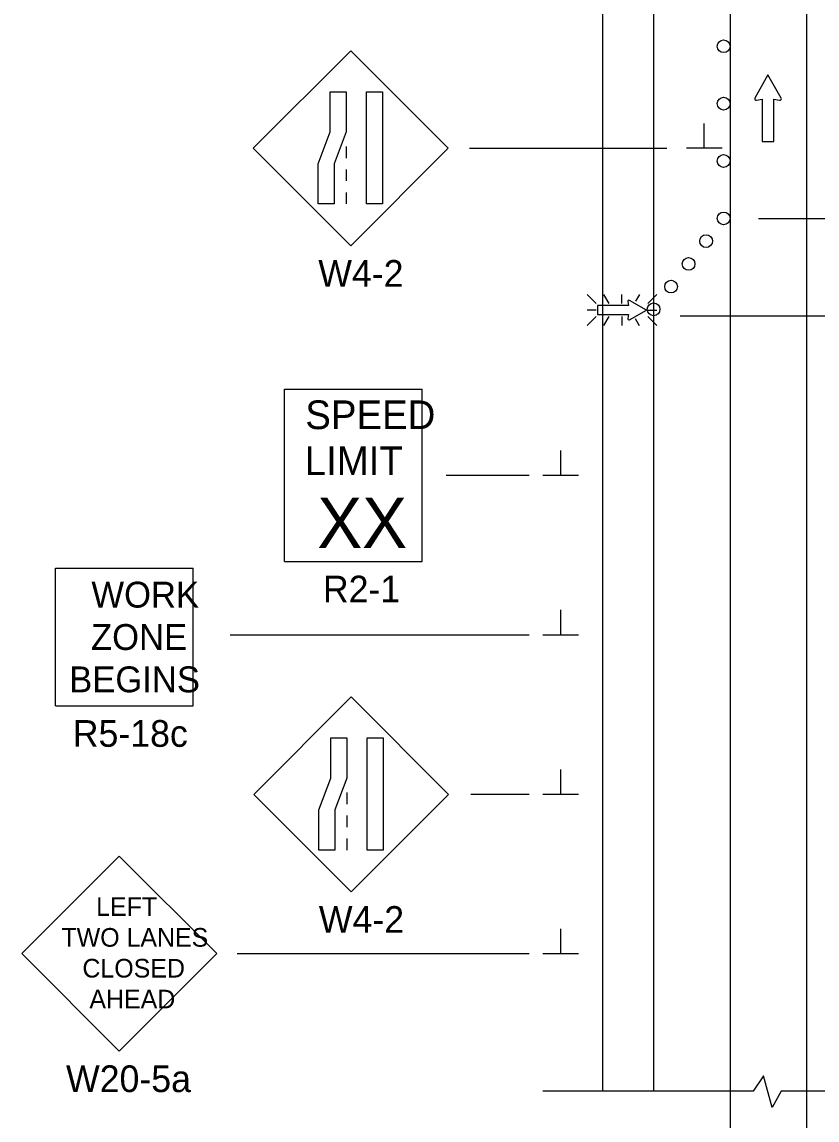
# Model space of a CAD drawing. Extents: x 16726 to 18475, y 7014 to 8214.
# Drawn here: x 16725.8 to 16975.3, y 7595.3 to 7939.7 of the extents above; entities that cross this region are included whole.
import ezdxf

# ---------------------------------------------------------------- set-up
doc = ezdxf.new("R2010")
doc.units = 0
for name, color, linetype in [('ALI_LEGAL_EX', 7, 'Continuous'), ('MT_SCRATCH_LEVEL_E', 7, 'Continuous'), ('PAVT_EDGE_EX', 7, 'Continuous'), ('TRAFFIC_SIGNS_PR', 7, 'Continuous'), ('TYPICAL_TEXT_DIMEN_PR', 7, 'Continuous')]:
    doc.layers.add(name, color=color, linetype=linetype)

msp = doc.modelspace()

# ---------------------------------------------------------------- linework, layer by layer
at = {"layer": 'ALI_LEGAL_EX'}
for p, q in [((16947.99, 8191.42), (16947.99, 7362.23)), ((16971.99, 8191.42), (16971.99, 7362.23)), ((16971.99, 8191.42), (16971.99, 7362.23))]:
    msp.add_line(p, q, dxfattribs=at)
for points in [[(16947.99, 7891.42), (16947.99, 7866.42)], [(16971.99, 7891.42), (16971.99, 7866.42)], [(16947.99, 7791.42), (16947.99, 7766.42)], [(16971.99, 7791.42), (16971.99, 7766.42)], [(16947.99, 7641.42), (16947.99, 7616.42)], [(16971.99, 7641.42), (16971.99, 7616.42)]]:
    msp.add_lwpolyline(points, dxfattribs=at)
at = {"layer": 'MT_SCRATCH_LEVEL_E'}
for p, q in [((16959.89, 7923.03), (16955.78, 7915.78)), ((16964.04, 7915.78), (16959.89, 7923.03)), ((16956.26, 7915.1), (16958.04, 7915.41)), ((16958.04, 7915.41), (16958.04, 7902.16)), ((16961.78, 7902.16), (16961.78, 7915.41)), ((16961.78, 7915.41), (16963.56, 7915.1)), ((16958.04, 7902.16), (16961.78, 7902.16))]:
    msp.add_line(p, q, dxfattribs=at)
for centre, start, end in [((16956.19, 7915.56), 150.4248, 279.9638), ((16963.63, 7915.56), 260.0362, 29.7731)]:
    msp.add_arc(centre, 0.463, start, end, dxfattribs=at)
at = {"layer": 'PAVT_EDGE_EX'}
for p, q in [((16907.99, 8214.3), (16907.99, 7604.34)), ((16923.99, 8214.3), (16923.99, 7604.34))]:
    msp.add_line(p, q, dxfattribs=at)
at = {"layer": 'TRAFFIC_SIGNS_PR'}
for p, q in [((16828.98, 7930.58), (16798.43, 7900.03)), ((16859.53, 7900.03), (16828.98, 7930.58)), ((16798.43, 7900.03), (16828.98, 7869.49)), ((16827.58, 7900.59), (16827.58, 7896.99)), ((16828.98, 7869.49), (16859.53, 7900.03)), ((16827.58, 7893.39), (16827.58, 7889.79)), ((16827.58, 7886.19), (16827.58, 7882.59)), ((16906.01, 7851.34), (16903.19, 7854.16)), ((16908.3, 7854.16), (16909.93, 7851.34)), ((16914.09, 7851.34), (16914.09, 7854.16)), ((16919.56, 7854.16), (16918.35, 7852.06)), ((16924.99, 7854.15), (16922.18, 7851.34)), ((16906.01, 7849.31), (16903.19, 7849.31)), ((16922.18, 7849.31), (16924.99, 7849.31)), ((16906.01, 7847.27), (16903.19, 7844.45)), ((16909.96, 7847.27), (16908.33, 7844.45)), ((16914.09, 7847.27), (16914.09, 7844.45)), ((16918.27, 7846.64), (16919.53, 7844.45)), ((16924.99, 7844.45), (16922.18, 7847.27)), ((16808.25, 7824.5), (16851.45, 7824.5)), ((16808.25, 7770.5), (16808.25, 7824.5)), ((16851.45, 7770.5), (16851.45, 7824.5)), ((16808.25, 7770.5), (16851.45, 7770.5)), ((16736.38, 7725.21), (16736.38, 7768.41)), ((16736.38, 7768.41), (16779.58, 7768.41)), ((16779.58, 7725.21), (16779.58, 7768.41)), ((16829.17, 7727.96), (16798.62, 7697.41)), ((16859.71, 7697.41), (16829.17, 7727.96)), ((16736.38, 7725.21), (16779.58, 7725.21)), ((16798.62, 7697.41), (16829.17, 7666.87)), ((16827.76, 7697.97), (16827.76, 7694.37)), ((16829.17, 7666.87), (16859.71, 7697.41)), ((16827.76, 7690.77), (16827.76, 7687.17)), ((16827.76, 7683.57), (16827.76, 7679.97)), ((16756.39, 7678.02), (16725.84, 7647.48)), ((16786.93, 7647.48), (16756.39, 7678.02)), ((16725.84, 7647.48), (16756.39, 7616.93)), ((16756.39, 7616.93), (16786.93, 7647.48))]:
    msp.add_line(p, q, dxfattribs=at)
for points in [[(16827.58, 7917.74), (16827.58, 7905.16), (16823.81, 7895.17), (16823.81, 7882.59), (16818.76, 7882.59), (16818.76, 7895.17), (16822.52, 7905.16), (16822.52, 7917.74)], [(16838.98, 7917.74), (16838.98, 7882.59), (16833.93, 7882.59), (16833.93, 7917.74)], [(16827.76, 7715.12), (16827.76, 7702.54), (16824, 7692.55), (16824, 7679.97), (16818.95, 7679.97), (16818.95, 7692.55), (16822.71, 7702.54), (16822.71, 7715.12)], [(16839.17, 7715.12), (16839.17, 7679.97), (16834.11, 7679.97), (16834.11, 7715.12)]]:
    msp.add_lwpolyline(points, close=True, dxfattribs=at)
for points in [[(16915.92, 7851.99), (16916.15, 7850.69), (16906.42, 7850.69), (16906.42, 7847.95), (16916.15, 7847.95), (16915.92, 7846.64)], [(16916.42, 7846.29), (16921.73, 7849.31), (16916.42, 7852.35)]]:
    msp.add_lwpolyline(points, dxfattribs=at)
for centre in [(16945.99, 7932.05), (16945.99, 7914.05), (16945.99, 7896.05), (16945.99, 7878.05), (16940.49, 7870.92), (16934.99, 7863.79), (16929.49, 7856.66), (16924, 7849.54)]:
    msp.add_circle(centre, 2, dxfattribs=at)
for centre, start, end in [((16916.25, 7852.05), 61.4833, 189.9593), ((16916.25, 7846.59), 170.7308, 298.8916)]:
    msp.add_arc(centre, 0.341, start, end, dxfattribs=at)
at = {"layer": 'TYPICAL_TEXT_DIMEN_PR'}
for p, q in [((16939.91, 7900.05), (16939.91, 7907.84)), ((16866.25, 7900.05), (16928.18, 7900.05)), ((16945.54, 7900.05), (16934.29, 7900.05)), ((16956.89, 7878.05), (17088.03, 7878.05)), ((16932.38, 7847.49), (17086.42, 7847.49)), ((16894.86, 7797.49), (16894.86, 7805.27)), ((16894.86, 7797.49), (16894.86, 7805.27)), ((16858.91, 7797.49), (16884.99, 7797.49)), ((16858.99, 7797.49), (16884.99, 7797.49)), ((16889.24, 7797.49), (16900.49, 7797.49)), ((16889.24, 7797.49), (16900.49, 7797.49)), ((16894.86, 7747.49), (16894.86, 7755.27)), ((16894.86, 7747.49), (16894.86, 7755.27)), ((16791.13, 7747.49), (16884.99, 7747.49)), ((16858.99, 7747.49), (16884.99, 7747.49)), ((16889.24, 7747.49), (16900.49, 7747.49)), ((16889.24, 7747.49), (16900.49, 7747.49)), ((16894.86, 7697.49), (16894.86, 7705.27)), ((16894.86, 7697.49), (16894.86, 7705.27)), ((16866.66, 7697.49), (16884.99, 7697.49)), ((16889.24, 7697.49), (16900.49, 7697.49)), ((16889.24, 7697.49), (16900.49, 7697.49)), ((16894.86, 7647.49), (16894.86, 7655.27)), ((16793.37, 7647.49), (16884.99, 7647.49)), ((16889.24, 7647.49), (16900.49, 7647.49)), ((16958.5, 7609.14), (16955.24, 7604.34)), ((16961.24, 7599.2), (16958.5, 7609.14)), ((16955.24, 7604.34), (16889.3, 7604.34)), ((16963.98, 7604.34), (16961.24, 7599.2)), ((17026.32, 7604.34), (16963.98, 7604.34))]:
    msp.add_line(p, q, dxfattribs=at)

# ---------------------------------------------------------------- texts
at = {"layer": 'TRAFFIC_SIGNS_PR'}
for s, height, p in [('W4-2', 8.37, (16818.81, 7856.62)), ('SPEED', 9, (16814.74, 7811.97)), ('LIMIT', 9, (16814.56, 7797.57)), ('XX', 15.785, (16818.5, 7774.73)), ('R2-1', 8.37, (16820.26, 7757.63)), ('WORK', 8.119, (16747.63, 7756)), ('ZONE', 8.119, (16747.5, 7742.71)), ('BEGINS', 8.119, (16740.66, 7729.43)), ('R5-18c', 8.37, (16741.79, 7712.34)), ('LEFT', 5.85, (16749.11, 7659.33)), ('W4-2', 8.37, (16818.99, 7654)), ('TWO LANES', 5.85, (16738.23, 7649.65)), ('CLOSED', 5.85, (16744.81, 7639.98)), ('AHEAD', 5.85, (16747, 7630.3)), ('W20-5a', 8.37, (16739.67, 7604.06))]:
    msp.add_text(s, height=height, dxfattribs=at).set_placement(p)

doc.saveas('drawing.dxf')
